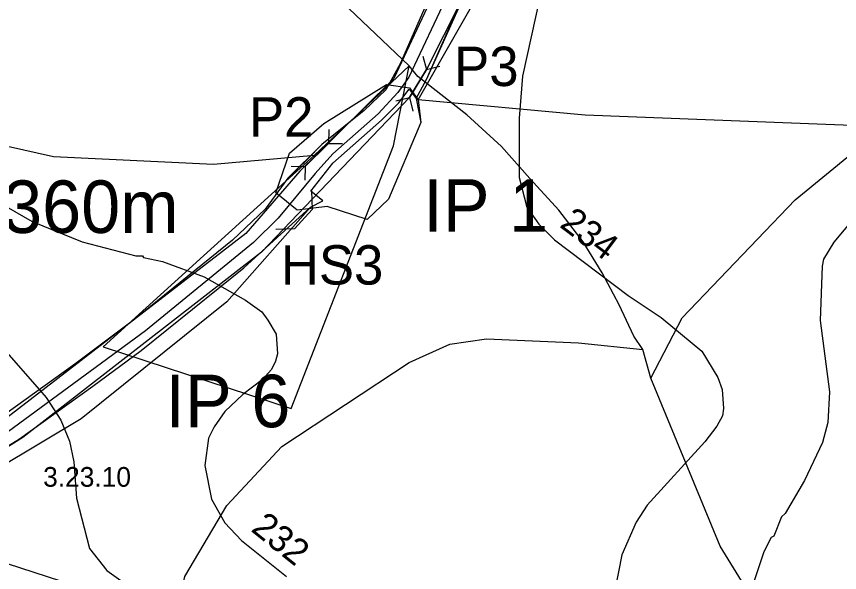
# Model space of a CAD drawing. Extents: x -662500 to -653478, y -1056827 to -1049993.
# Drawn here: x -660921.6 to -660608.1, y -1052767 to -1052555.2 of the extents above; entities that cross this region are included whole.
import ezdxf

# ---------------------------------------------------------------- set-up
doc = ezdxf.new("R2010")
doc.units = 0
for name, color, linetype in [('Vrstva 10', 7, 'Continuous'), ('Vrstva 17', 7, 'Continuous'), ('Vrstva 18', 7, 'Continuous'), ('Vrstva 24', 7, 'Continuous'), ('Vrstva 5', 7, 'Continuous'), ('Vrstva 51', 7, 'Continuous'), ('Vrstva 52', 7, 'Continuous'), ('Vrstva 57', 7, 'Continuous'), ('Vrstva 61', 7, 'Continuous'), ('Vrstva 7', 7, 'Continuous')]:
    doc.layers.add(name, color=color, linetype=linetype)

# ---------------------------------------------------------------- blocks, each defined once
blk = doc.blocks.new('PSZ019')
at = {"layer": 'Vrstva 17'}
blk.add_lwpolyline([(-10, -5), (-5, 0), (5, 0), (10, -5)], dxfattribs=at)
blk = doc.blocks.new('PSZ017')
at = {"layer": 'Vrstva 17'}
for points in [[(-10, 3.75), (-6.25, 0), (-10, -3.75)], [(10, 3.75), (6.25, 0), (10, -3.75)], [(-6.25, 0), (6.25, 0)]]:
    blk.add_lwpolyline(points, dxfattribs=at)

msp = doc.modelspace()

# ---------------------------------------------------------------- linework, layer by layer
at = {"layer": 'Vrstva 10'}
msp.add_lwpolyline([(-660730.96, -1052491.07), (-660742.4, -1052515.29), (-660772.11, -1052578.35), (-660776.37, -1052584.21), (-660783.83, -1052592.29), (-660801.06, -1052607.48), (-660807.81, -1052615.02), (-660821.93, -1052631.99), (-660831.3, -1052641.31), (-660872.41, -1052674.97), (-660929.03, -1052716.48), (-660971.55, -1052741.79), (-660975.1, -1052744.68)], dxfattribs=at)
at = {"layer": 'Vrstva 24'}
for points in [[(-660772, -1052574), (-660874.5, -1052476.5), (-660885, -1052465), (-660916, -1052440.5), (-660936, -1052426), (-660954.5, -1052417.5), (-660980.5, -1052408), (-661038, -1052393), (-661089.5, -1052368.5), (-661136, -1052338), (-661184, -1052312.5), (-661189, -1052307)], [(-660680, -1052693), (-660668, -1052670), (-660625, -1052625), (-660559, -1052571), (-660471.5, -1052512.5), (-660425, -1052485), (-660396.5, -1052473), (-660357, -1052462), (-660276, -1052455), (-660243.5, -1052445.5), (-660138, -1052390)], [(-660808, -1052608), (-660888.5, -1052681), (-660817, -1052704.5), (-660778, -1052604.5), (-660772, -1052574)], [(-660808, -1052608), (-660772, -1052574)], [(-660683, -1052682), (-660686.4, -1052677), (-660691.99, -1052665.07), (-660698.52, -1052652.91), (-660705.76, -1052641.07), (-660714.93, -1052629.04), (-660725.99, -1052616.89), (-660736.84, -1052604.8), (-660750.08, -1052592.71), (-660768.76, -1052578.04), (-660772, -1052574)], [(-660980.5, -1052589.5), (-660959, -1052597), (-660907.5, -1052608.5), (-660846.5, -1052611.5), (-660808, -1052608)], [(-660781, -1052927), (-660835.5, -1052885.5), (-660852, -1052867.5), (-660862.5, -1052840.5), (-660865.5, -1052804.5), (-660857.5, -1052768.5), (-660841.5, -1052741.5), (-660820.5, -1052719), (-660772, -1052687), (-660756.5, -1052680), (-660742.5, -1052678), (-660707.5, -1052679.5), (-660683, -1052682)], [(-660680, -1052693), (-660683, -1052682)], [(-660420, -1052937), (-660474.5, -1052915), (-660540, -1052878.5), (-660592, -1052838), (-660628.5, -1052797.5), (-660653.5, -1052757), (-660680, -1052693)]]:
    msp.add_lwpolyline(points, dxfattribs=at)
at = {"layer": 'Vrstva 5'}
for points in [[(-660928.32, -1052328.06), (-660917.49, -1052330.86), (-660907.97, -1052335.35), (-660898.69, -1052342.31), (-660857.15, -1052383.85), (-660778.08, -1052461.12), (-660757.6, -1052480.26), (-660749.09, -1052487.66), (-660743.24, -1052493.84), (-660743.39, -1052500.66), (-660745.7, -1052507.75), (-660755.18, -1052527.06), (-660775.44, -1052573.22), (-660780.95, -1052583.18), (-660789.17, -1052591), (-660805.31, -1052603.95), (-660810.6, -1052609.41), (-660818.19, -1052616.74), (-660826.8, -1052628.64), (-660839.31, -1052640.39), (-660876.46, -1052670.55), (-660899.32, -1052687.63), (-660925.98, -1052706.8)], [(-660928.32, -1052328.06), (-660917.49, -1052330.86), (-660907.97, -1052335.35), (-660898.69, -1052342.31), (-660857.15, -1052383.85), (-660778.08, -1052461.12), (-660757.6, -1052480.26), (-660749.09, -1052487.66), (-660743.24, -1052493.84), (-660743.39, -1052500.66), (-660745.7, -1052507.75), (-660755.18, -1052527.06), (-660775.44, -1052573.22), (-660780.95, -1052583.18), (-660789.17, -1052591), (-660805.31, -1052603.95), (-660818.19, -1052616.74), (-660826.8, -1052628.64), (-660839.31, -1052640.39), (-660876.46, -1052670.55), (-660899.32, -1052687.63), (-660925.98, -1052706.8)], [(-660963.87, -1052742.7), (-660920.45, -1052716.01), (-660892.53, -1052696.06), (-660874.07, -1052682.42), (-660835.01, -1052650.9), (-660809.61, -1052627.89), (-660804.83, -1052625.49), (-660809.42, -1052621.74), (-660801.02, -1052611.14), (-660782.55, -1052594.75), (-660776.11, -1052588.25), (-660771.96, -1052582.87), (-660769.37, -1052586.51), (-660765.45, -1052579.22), (-660733.95, -1052509.32), (-660729.44, -1052503.44), (-660724.58, -1052500.5), (-660715.51, -1052501.44), (-660658.01, -1052521.57), (-660649.17, -1052523.99), (-660636.46, -1052526.02), (-660620.21, -1052526.77), (-660597.01, -1052526.32)], [(-660963.87, -1052742.7), (-660920.45, -1052716.01), (-660892.53, -1052696.06), (-660874.07, -1052682.42), (-660835.01, -1052650.9), (-660809.61, -1052627.89), (-660804.83, -1052625.49), (-660809.42, -1052621.74), (-660801.02, -1052611.14), (-660782.55, -1052594.75), (-660776.11, -1052588.25), (-660771.96, -1052582.87), (-660769.37, -1052586.51), (-660765.45, -1052579.22), (-660744.66, -1052532.13)], [(-660771.96, -1052582.87), (-660769.37, -1052586.51), (-660767.55, -1052595.54)]]:
    msp.add_lwpolyline(points, dxfattribs=at)
at = {"layer": 'Vrstva 51'}
msp.add_lwpolyline([(-661333.87, -1052639.96), (-661030.97, -1052722.69), (-660970.26, -1052748.97), (-660859.83, -1052784.77), (-660719.81, -1052919.67), (-660703.56, -1053036.33), (-660627.44, -1053034.97), (-660487.78, -1053023.58), (-660465.78, -1053017.23), (-660435.07, -1052998.4)], dxfattribs=at)
at = {"layer": 'Vrstva 52'}
for points in [[(-660768.57, -1052587.01), (-660724.21, -1052509.24), (-660640.37, -1052537), (-660593.93, -1052532.78), (-660534.66, -1052516.97)], [(-660809.61, -1052627.89), (-660841.41, -1052663.91), (-660896.9, -1052708.39), (-660944.8, -1052737.02)]]:
    msp.add_lwpolyline(points, dxfattribs=at)
msp.add_lwpolyline([(-660817.63, -1052607.34), (-660804.53, -1052595.93), (-660780.64, -1052581.11), (-660771.91, -1052582.42), (-660768.57, -1052587.01), (-660767.55, -1052595.54), (-660779.87, -1052624.78), (-660787.96, -1052632.52), (-660803.24, -1052627.54), (-660814.67, -1052628.98), (-660822.76, -1052622.42)], close=True, dxfattribs=at)
at = {"layer": 'Vrstva 57'}
msp.add_lwpolyline([(-660240.14, -1052589.03), (-660367.97, -1052599.37), (-660411.21, -1052606.42), (-660478.88, -1052627.1), (-660527.29, -1052616.29), (-660561.13, -1052608.3), (-660596.85, -1052597.02), (-660704.94, -1052592.79), (-660768.57, -1052587.01)], dxfattribs=at)
at = {"layer": 'Vrstva 61'}
for points in [[(-660738.08, -1052494.07), (-660777.88, -1052578.81), (-660800.49, -1052601.16), (-660813.62, -1052614.14), (-660834.28, -1052637.91), (-660925.3, -1052708.08), (-660970.85, -1052736.56)], [(-660726.22, -1052497.62), (-660765.46, -1052575.43), (-660771.92, -1052586.13), (-660808.78, -1052624.64), (-660828.23, -1052644.96), (-660919.18, -1052715.59), (-660965.2, -1052744.53)]]:
    msp.add_lwpolyline(points, dxfattribs=at)
at = {"layer": 'Vrstva 7'}
for p, q in [((-660719.16, -1052533.52), (-660728.79, -1052578.02)), ((-660719.16, -1052533.52), (-660728.79, -1052578.02)), ((-660728.79, -1052578.02), (-660730.07, -1052593.89)), ((-660728.79, -1052578.02), (-660730.07, -1052593.89)), ((-660730.07, -1052593.89), (-660730.07, -1052616.56)), ((-660730.07, -1052593.89), (-660730.07, -1052616.56)), ((-660730.07, -1052616.56), (-660727.23, -1052627.9)), ((-660730.07, -1052616.56), (-660727.23, -1052627.9)), ((-660935.98, -1052621.66), (-660915.58, -1052633.28)), ((-660727.23, -1052627.9), (-660722.56, -1052634.28)), ((-660727.23, -1052627.9), (-660722.56, -1052634.28)), ((-660915.58, -1052633.28), (-660896.58, -1052641.08)), ((-660602.38, -1052631.73), (-660610.18, -1052641.22)), ((-660722.56, -1052634.28), (-660716.6, -1052640.23)), ((-660722.56, -1052634.28), (-660716.6, -1052640.23)), ((-660716.6, -1052640.23), (-660688.55, -1052661.49)), ((-660716.6, -1052640.23), (-660688.55, -1052661.49)), ((-660896.58, -1052641.08), (-660876.18, -1052646.32)), ((-660610.18, -1052641.22), (-660614.14, -1052647.6)), ((-660876.18, -1052646.32), (-660873.63, -1052646.32)), ((-660873.63, -1052646.32), (-660873.2, -1052647.03)), ((-660873.2, -1052647.03), (-660865.97, -1052648.59)), ((-660865.97, -1052648.59), (-660850.1, -1052654.4)), ((-660614.14, -1052647.6), (-660614.71, -1052650.29)), ((-660614.71, -1052650.29), (-660615.42, -1052670.98)), ((-660850.1, -1052654.4), (-660834.31, -1052663.22)), ((-660688.55, -1052661.49), (-660676.07, -1052669.85)), ((-660688.55, -1052661.49), (-660676.07, -1052669.85)), ((-660834.31, -1052663.22), (-660828.14, -1052667.72)), ((-660828.14, -1052667.72), (-660825.87, -1052670.84)), ((-660825.87, -1052670.84), (-660822.61, -1052676.22)), ((-660676.07, -1052669.85), (-660660.48, -1052682.74)), ((-660676.07, -1052669.85), (-660660.48, -1052682.74)), ((-660615.42, -1052670.98), (-660611.88, -1052698.19)), ((-660931.87, -1052675.66), (-660910.33, -1052700.32)), ((-660822.61, -1052676.22), (-660822.18, -1052683.74)), ((-660822.18, -1052683.74), (-660822.9, -1052686.44)), ((-660660.48, -1052682.74), (-660654.39, -1052692.66)), ((-660660.48, -1052682.74), (-660654.39, -1052692.66)), ((-660822.9, -1052686.44), (-660824.45, -1052689.69)), ((-660824.45, -1052689.69), (-660827.99, -1052693.66)), ((-660827.99, -1052693.66), (-660835.36, -1052699.18)), ((-660654.39, -1052692.66), (-660652.83, -1052697.34)), ((-660654.39, -1052692.66), (-660652.83, -1052697.34)), ((-660835.36, -1052699.18), (-660842.17, -1052705.7)), ((-660652.83, -1052697.34), (-660652.27, -1052704.57)), ((-660652.83, -1052697.34), (-660652.27, -1052704.57)), ((-660611.88, -1052698.19), (-660612.58, -1052709.81)), ((-660910.33, -1052700.32), (-660904.66, -1052708.96)), ((-660842.17, -1052705.7), (-660846.28, -1052711.51)), ((-660652.27, -1052704.57), (-660652.69, -1052707.26)), ((-660652.27, -1052704.57), (-660652.69, -1052707.26)), ((-660904.66, -1052708.96), (-660901.4, -1052716.9)), ((-660652.69, -1052707.26), (-660654.82, -1052711.23)), ((-660652.69, -1052707.26), (-660654.82, -1052711.23)), ((-660846.28, -1052711.51), (-660848.4, -1052715.76)), ((-660654.82, -1052711.23), (-660659.35, -1052717.18)), ((-660654.82, -1052711.23), (-660659.35, -1052717.18)), ((-660612.58, -1052709.81), (-660614.57, -1052717.46)), ((-660901.4, -1052716.9), (-660899.7, -1052724.83)), ((-660848.4, -1052715.76), (-660849.82, -1052726.25)), ((-660659.35, -1052717.18), (-660681.32, -1052741.27)), ((-660659.35, -1052717.18), (-660681.32, -1052741.27)), ((-660614.57, -1052717.46), (-660621.37, -1052731.92)), ((-660899.7, -1052724.83), (-660898.71, -1052738.72)), ((-660849.82, -1052726.25), (-660847.27, -1052739)), ((-660621.37, -1052731.92), (-660628.74, -1052744.53)), ((-660898.71, -1052738.72), (-660893.75, -1052757.85)), ((-660847.27, -1052739), (-660842.17, -1052748.07)), ((-660681.32, -1052741.27), (-660685.57, -1052747.79)), ((-660681.32, -1052741.27), (-660685.57, -1052747.79)), ((-660630.16, -1052745.81), (-660633.13, -1052753.18)), ((-660628.74, -1052744.53), (-660630.16, -1052745.81)), ((-660842.17, -1052748.07), (-660835.93, -1052754.74)), ((-660685.57, -1052747.79), (-660690.95, -1052760.26)), ((-660685.57, -1052747.79), (-660690.95, -1052760.26)), ((-660633.13, -1052753.18), (-660634.12, -1052753.6)), ((-660835.93, -1052754.74), (-660818.78, -1052768.48)), ((-660634.12, -1052753.6), (-660636.96, -1052759.13)), ((-660893.75, -1052757.85), (-660887.23, -1052766.21)), ((-660636.96, -1052759.13), (-660640.64, -1052770.18)), ((-660690.95, -1052760.26), (-660693.65, -1052773.87)), ((-660690.95, -1052760.26), (-660693.65, -1052773.87)), ((-660887.23, -1052766.21), (-660878.3, -1052772.59))]:
    msp.add_line(p, q, dxfattribs=at)

# ---------------------------------------------------------------- block references
at = {"layer": 'Vrstva 17'}
for name, p, rotation in [('PSZ017', (-660768.69, -1052580.78), 58.88959889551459), ('PSZ017', (-660807.18, -1052607.94), 44.17131967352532), ('PSZ019', (-660812.3, -1052632.37), -132.4195672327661)]:
    msp.add_blockref(name, p, dxfattribs=dict(at, rotation=rotation))

# ---------------------------------------------------------------- texts
for s, p in [('P3', (-660754.86, -1052581.72)), ('P2', (-660833, -1052600.97)), ('HS3', (-660820.87, -1052657.33))]:
    msp.add_text(s, height=15, rotation=360, dxfattribs=at).set_placement(p)
at = {"layer": 'Vrstva 18'}
msp.add_text('C4-360m', height=20, rotation=360, dxfattribs=at).set_placement((-660969.79, -1052637.67))
at = {"layer": 'Vrstva 24'}
msp.add_text('3.23.10', height=7.5, dxfattribs=at).set_placement((-660911.43, -1052734.31))
at = {"layer": 'Vrstva 52'}
for s, p in [('IP 1', (-660766.64, -1052637.19)), ('IP 6', (-660864.85, -1052711.66))]:
    msp.add_text(s, height=20, dxfattribs=at).set_placement(p)
at = {"layer": 'Vrstva 7'}
for s, rotation, p in [('234', 322.8531, (-660715.08, -1052635.11)), ('232', 321.284, (-660832.64, -1052750.96))]:
    msp.add_text(s, height=10, rotation=rotation, dxfattribs=at).set_placement(p)

doc.saveas('drawing.dxf')
